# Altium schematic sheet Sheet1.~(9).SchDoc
size A4
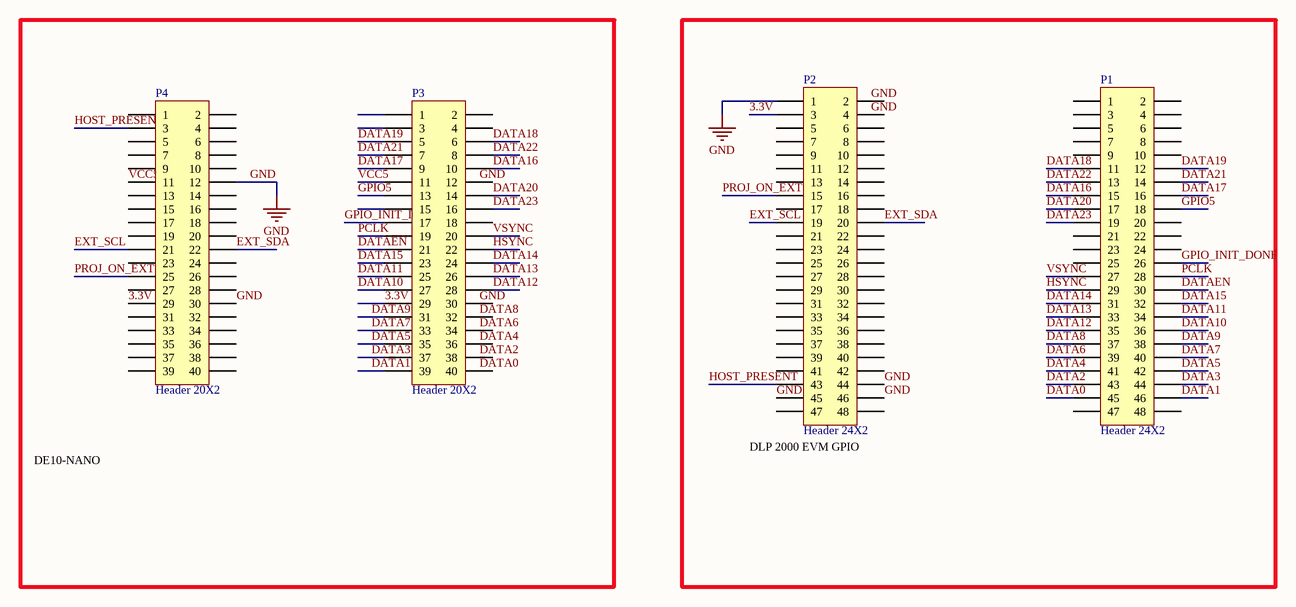
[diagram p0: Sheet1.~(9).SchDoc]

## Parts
P1  Header 24X2  [HDR2X24]
P2  Header 24X2  [HDR2X24]
P3  Header 20X2  [HDR2X20]
P4  Header 20X2  [HDR2X20]

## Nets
GND: P2.1 P2.44 P2.45 P2.46 P4.12 P4.30
3.3V: P2.3 P3.29 P4.29
DATA0: P1.45
DATA1: P1.46 P3.39
DATA2: P1.43
DATA3: P1.44 P3.37
DATA4: P1.41
DATA5: P1.42 P3.35
DATA6: P1.39
DATA7: P1.40 P3.33
DATA8: P1.37
DATA9: P1.38 P3.31
DATA10: P1.36 P3.27
DATA11: P1.34 P3.25
DATA12: P1.35 P3.28
DATA13: P1.33 P3.26
DATA14: P1.31 P3.24
DATA15: P1.32 P3.23
DATA16: P1.15 P3.10
DATA17: P1.16 P3.9
DATA18: P1.11 P3.6
DATA19: P1.12 P3.5
DATA20: P1.17 P3.14
DATA21: P1.14 P3.7
DATA22: P1.13 P3.8
DATA23: P1.19 P3.16
DATAEN: P1.30 P3.21
EXT_SCL: P2.19 P4.21
EXT_SDA: P2.20 P4.22
GPIO5: P1.18 P3.13
GPIO_INIT_DONE: P1.26 P3.17
HOST_PRESENT: P2.43 P4.3
HSYNC: P1.29 P3.22
PCLK: P1.28 P3.19
PROJ_ON_EXT: P2.15 P4.25
VCC5: P3.11 P4.11
VSYNC: P1.27 P3.20

Not connected (* = marked no-connect by the designer): P1 1 2 3 4 5 6 7 8 9 10 20 21 22 23 24 25 47 48; P2 2 4 5 6 7 8 9 10 11 12 13 14 16 17 18 21 22 23 24 25 26 27 28 29 30 31 32 33 34 35 36 37 38 39 40 41 42 47 48; P3 1 2 3 4 12 15 18 30 32 34 36 38 40; P4 1 2 4 5 6 7 8 9 10 13 14 15 16 17 18 19 20 23 24 26 27 28 31 32 33 34 35 36 37 38 39 40

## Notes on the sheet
- DE10-NANO
- DLP 2000 EVM GPIO
- Labels drawn without touching a wire or pin: DATA0, DATA2, DATA4, DATA6, DATA8, GND

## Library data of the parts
P1 P2 = Header 24X2: Header, 24-Pin, Dual row
P3 P4 = Header 20X2: Header, 20-Pin, Dual row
